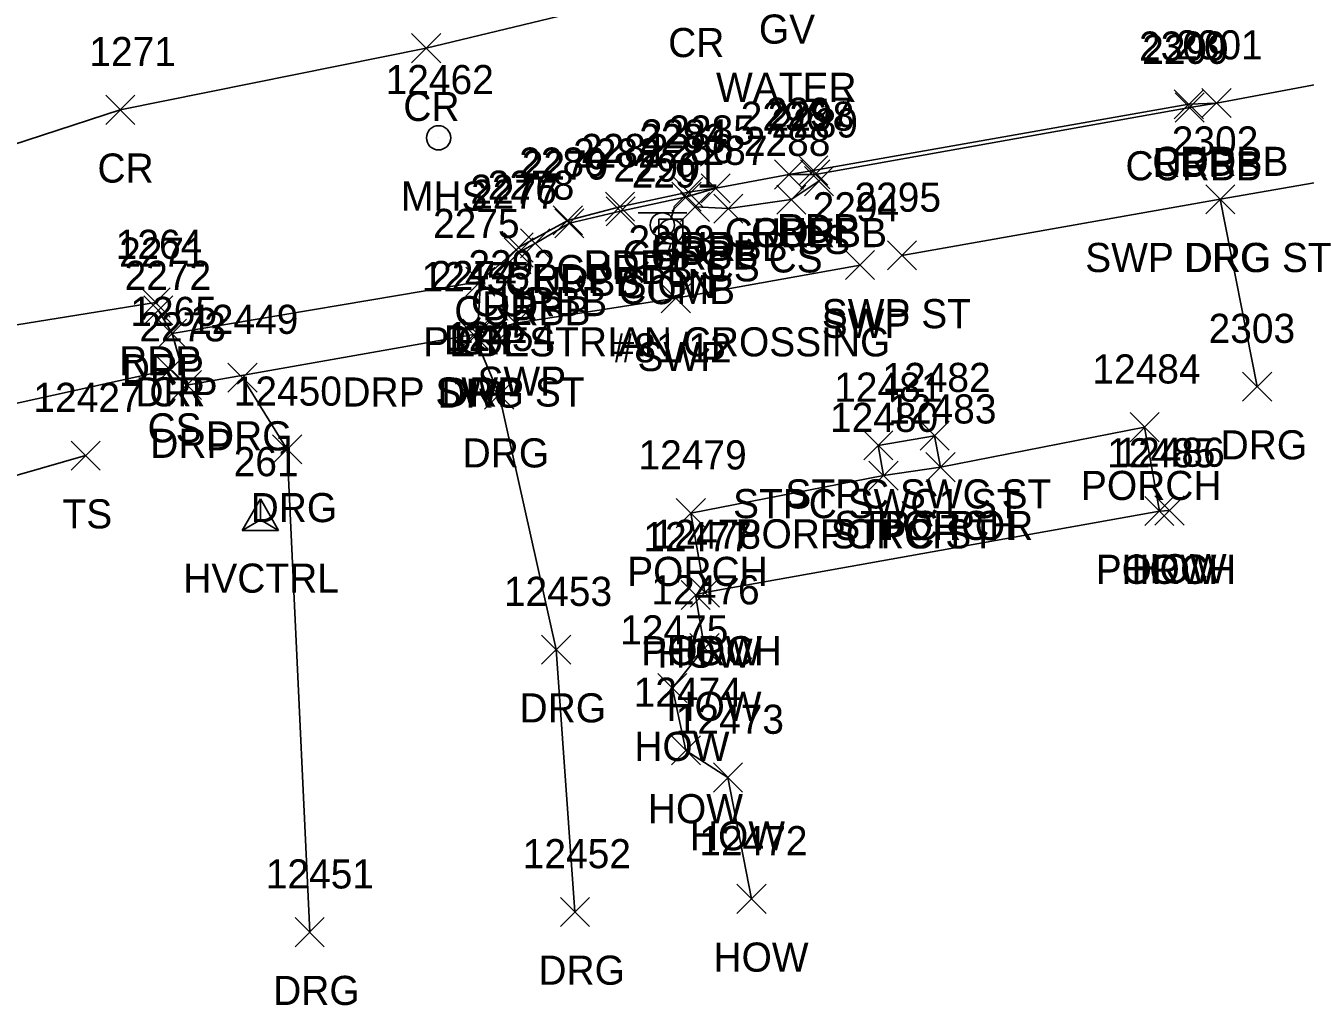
# Model space of a CAD drawing. Extents: x 1769141 to 1770817, y 735471 to 742405.
# Drawn here: x 1770233.5 to 1770321.5, y 741060.7 to 741128 of the extents above; entities that cross this region are included whole.
import ezdxf

# ---------------------------------------------------------------- set-up
doc = ezdxf.new("R2010")
doc.units = 0
for name, color, linetype in [('C_A', 7, 'Continuous'), ('C_I', 7, 'Continuous'), ('CPSM', 7, 'Continuous'), ('L_A', 7, 'Continuous'), ('L_I', 7, 'Continuous'), ('L_TIC', 7, 'Continuous'), ('LBC', 7, 'Continuous'), ('LBF', 7, 'Continuous'), ('LELB', 7, 'Continuous'), ('P_A', 7, 'Continuous'), ('P_I', 7, 'Continuous'), ('P_TIC', 7, 'Continuous'), ('PET', 7, 'Continuous'), ('PRC', 7, 'Continuous'), ('R_A', 7, 'Continuous'), ('R_I', 7, 'Continuous'), ('R_TIC', 7, 'Continuous'), ('RC', 7, 'Continuous'), ('RDG', 7, 'Continuous'), ('RDP', 7, 'Continuous'), ('RSW', 7, 'Continuous'), ('S_A', 7, 'Continuous'), ('S_C', 7, 'Continuous'), ('S_I', 7, 'Continuous'), ('SSGN', 7, 'Continuous'), ('U_A', 7, 'Continuous'), ('U_C', 7, 'Continuous'), ('U_I', 7, 'Continuous'), ('UP', 7, 'Continuous'), ('USMH', 7, 'Continuous')]:
    doc.layers.add(name, color=color, linetype=linetype)

msp = doc.modelspace()

# ---------------------------------------------------------------- linework, layer by layer
at = {"layer": 'CPSM'}
for p, q in [((1770248.416, 741093.366), (1770249.666, 741095.531)), ((1770250.916, 741093.366), (1770249.666, 741095.531)), ((1770249.666, 741094.087), (1770249.666, 741095.531)), ((1770248.416, 741093.366), (1770249.666, 741094.087)), ((1770249.666, 741094.087), (1770249.666, 741094.087)), ((1770249.666, 741094.087), (1770250.916, 741093.366)), ((1770248.416, 741093.366), (1770250.916, 741093.366))]:
    msp.add_line(p, q, dxfattribs=at)
at = {"layer": 'L_TIC'}
for points in [[(1770287.046, 741116.348), (1770289.046, 741118.348)], [(1770289.046, 741116.348), (1770287.046, 741118.348)], [(1770285.142, 741115.079), (1770287.142, 741117.079)], [(1770287.142, 741115.079), (1770285.142, 741117.079)], [(1770278.529, 741114.58), (1770280.529, 741116.58)], [(1770280.529, 741114.58), (1770278.529, 741116.58)], [(1770280.82, 741114.467), (1770282.82, 741116.467)], [(1770282.82, 741114.467), (1770280.82, 741116.467)], [(1770242.463, 741103.407), (1770244.463, 741105.407)], [(1770244.463, 741103.407), (1770242.463, 741105.407)], [(1770309.427, 741099.454), (1770311.427, 741101.454)], [(1770311.427, 741099.454), (1770309.427, 741101.454)], [(1770291.118, 741098.206), (1770293.118, 741100.206)], [(1770293.118, 741098.206), (1770291.118, 741100.206)], [(1770294.996, 741098.871), (1770296.996, 741100.871)], [(1770296.996, 741098.871), (1770294.996, 741100.871)], [(1770236.65, 741097.502), (1770238.65, 741099.502)], [(1770238.65, 741097.502), (1770236.65, 741099.502)], [(1770295.4, 741096.707), (1770297.4, 741098.707)], [(1770297.4, 741096.707), (1770295.4, 741098.707)], [(1770295.4, 741096.707), (1770297.4, 741098.707)], [(1770297.4, 741096.707), (1770295.4, 741098.707)], [(1770291.48, 741096.13), (1770293.48, 741098.13)], [(1770293.48, 741096.13), (1770291.48, 741098.13)], [(1770291.48, 741096.13), (1770293.48, 741098.13)], [(1770293.48, 741096.13), (1770291.48, 741098.13)], [(1770311.137, 741093.735), (1770313.137, 741095.735)], [(1770313.137, 741093.735), (1770311.137, 741095.735)], [(1770278.244, 741093.551), (1770280.244, 741095.551)], [(1770280.244, 741093.551), (1770278.244, 741095.551)], [(1770310.442, 741093.695), (1770312.442, 741095.695)], [(1770312.442, 741093.695), (1770310.442, 741095.695)], [(1770310.442, 741093.695), (1770312.442, 741095.695)], [(1770312.442, 741093.695), (1770310.442, 741095.695)], [(1770278.568, 741087.934), (1770280.568, 741089.934)], [(1770280.568, 741087.934), (1770278.568, 741089.934)], [(1770279.211, 741088.103), (1770281.211, 741090.103)], [(1770281.211, 741088.103), (1770279.211, 741090.103)], [(1770279.211, 741088.103), (1770281.211, 741090.103)], [(1770281.211, 741088.103), (1770279.211, 741090.103)], [(1770279.177, 741084.285), (1770281.177, 741086.285)], [(1770281.177, 741084.285), (1770279.177, 741086.285)], [(1770276.972, 741081.536), (1770278.972, 741083.536)], [(1770278.972, 741081.536), (1770276.972, 741083.536)], [(1770277.902, 741077.257), (1770279.902, 741079.257)], [(1770279.902, 741077.257), (1770277.902, 741079.257)], [(1770280.793, 741075.397), (1770282.793, 741077.397)], [(1770282.793, 741075.397), (1770280.793, 741077.397)], [(1770282.41, 741067.062), (1770284.41, 741069.062)], [(1770284.41, 741067.062), (1770282.41, 741069.062)]]:
    msp.add_lwpolyline(points, dxfattribs=at)
at = {"layer": 'LBC'}
msp.add_lwpolyline([(1770283.41, 741068.062), (1770281.793, 741076.397), (1770278.902, 741078.257), (1770277.972, 741082.536), (1770280.177, 741085.285), (1770279.568, 741088.934), (1770280.211, 741089.103), (1770311.442, 741094.695), (1770312.137, 741094.735)], dxfattribs=at)
at = {"layer": 'LBF'}
for points in [[(1770280.211, 741089.103), (1770279.244, 741094.551), (1770292.48, 741097.13), (1770296.4, 741097.707), (1770310.427, 741100.454), (1770311.442, 741094.695)], [(1770292.48, 741097.13), (1770292.118, 741099.206), (1770295.996, 741099.871), (1770296.4, 741097.707)]]:
    msp.add_lwpolyline(points, dxfattribs=at)
at = {"layer": 'LELB'}
for points in [[(1770279.529, 741115.58), (1770281.82, 741115.467), (1770286.142, 741116.079), (1770288.046, 741117.348)], [(1770243.463, 741104.407), (1770229.687, 741101.394), (1770215.801, 741098.707), (1770201.283, 741096.576), (1770194.054, 741092.056)], [(1770198.356, 741087.687), (1770219.162, 741093.21), (1770237.65, 741098.502)]]:
    msp.add_lwpolyline(points, dxfattribs=at)
at = {"layer": 'P_TIC'}
for points in [[(1770260.05, 741125.482), (1770262.05, 741127.482)], [(1770262.05, 741125.482), (1770260.05, 741127.482)], [(1770239.032, 741121.25), (1770241.032, 741123.25)], [(1770241.032, 741121.25), (1770239.032, 741123.25)], [(1770312.467, 741121.626), (1770314.467, 741123.626)], [(1770314.467, 741121.626), (1770312.467, 741123.626)], [(1770314.364, 741121.711), (1770316.364, 741123.711)], [(1770316.364, 741121.711), (1770314.364, 741123.711)], [(1770284.981, 741116.808), (1770286.981, 741118.808)], [(1770286.981, 741116.808), (1770284.981, 741118.808)], [(1770286.654, 741117.086), (1770288.654, 741119.086)], [(1770288.654, 741117.086), (1770286.654, 741119.086)], [(1770279.95, 741115.863), (1770281.95, 741117.863)], [(1770281.95, 741115.863), (1770279.95, 741117.863)], [(1770278.067, 741115.593), (1770280.067, 741117.593)], [(1770280.067, 741115.593), (1770278.067, 741117.593)], [(1770273.372, 741114.598), (1770275.372, 741116.598)], [(1770275.372, 741114.598), (1770273.372, 741116.598)], [(1770269.791, 741113.659), (1770271.791, 741115.659)], [(1770271.791, 741113.659), (1770269.791, 741115.659)], [(1770266.402, 741111.794), (1770268.402, 741113.794)], [(1770268.402, 741111.794), (1770266.402, 741113.794)], [(1770263.782, 741109.448), (1770265.782, 741111.448)], [(1770265.782, 741109.448), (1770263.782, 741111.448)], [(1770241.459, 741108.014), (1770243.459, 741110.014)], [(1770243.459, 741108.014), (1770241.459, 741110.014)], [(1770242.587, 741105.881), (1770244.587, 741107.881)], [(1770244.587, 741105.881), (1770242.587, 741107.881)]]:
    msp.add_lwpolyline(points, dxfattribs=at)
at = {"layer": 'PET'}
for points in [[(1770267.402, 741112.794), (1770270.791, 741114.659), (1770274.372, 741115.598), (1770279.067, 741116.593), (1770280.95, 741116.863), (1770285.981, 741117.808), (1770287.654, 741118.086), (1770313.467, 741122.626), (1770315.364, 741122.711), (1770327.096, 741124.908), (1770329.296, 741125.38), (1770348.677, 741128.817), (1770381.373, 741134.55), (1770423.899, 741142.105)], [(1770147.313, 741084.024), (1770155.707, 741087.796), (1770162.831, 741089.417), (1770171.891, 741090.698), (1770171.852, 741092.948), (1770186.159, 741098.793), (1770191.681, 741100.4), (1770200.669, 741101.89), (1770211.537, 741103.665), (1770225.504, 741106.293), (1770242.459, 741109.014)]]:
    msp.add_lwpolyline(points, dxfattribs=at)
at = {"layer": 'PRC'}
for points in [[(1770422.288, 741154.401), (1770391.031, 741148.9), (1770351.212, 741141.744), (1770324.852, 741137.505), (1770305.015, 741134.401), (1770279.252, 741130.869), (1770261.05, 741126.482)], [(1770261.05, 741126.482), (1770240.032, 741122.25)], [(1770240.032, 741122.25), (1770223.985, 741117.036), (1770202.573, 741111.843), (1770190.375, 741109.654), (1770171.332, 741105.227), (1770161.251, 741102.786), (1770155.587, 741101.56), (1770143.323, 741098.229)], [(1770243.587, 741106.881), (1770264.782, 741110.448)]]:
    msp.add_lwpolyline(points, dxfattribs=at)
at = {"layer": 'R_TIC'}
for points in [[(1770312.527, 741121.406), (1770314.527, 741123.406)], [(1770314.527, 741121.406), (1770312.527, 741123.406)], [(1770314.364, 741121.711), (1770316.364, 741123.711)], [(1770316.364, 741121.711), (1770314.364, 741123.711)], [(1770284.981, 741116.808), (1770286.981, 741118.808)], [(1770286.981, 741116.808), (1770284.981, 741118.808)], [(1770286.782, 741116.816), (1770288.782, 741118.816)], [(1770288.782, 741116.816), (1770286.782, 741118.816)], [(1770279.95, 741115.863), (1770281.95, 741117.863)], [(1770281.95, 741115.863), (1770279.95, 741117.863)], [(1770277.946, 741115.281), (1770279.946, 741117.281)], [(1770279.946, 741115.281), (1770277.946, 741117.281)], [(1770314.627, 741115.109), (1770316.627, 741117.109)], [(1770316.627, 741115.109), (1770314.627, 741117.109)], [(1770314.627, 741115.109), (1770316.627, 741117.109)], [(1770316.627, 741115.109), (1770314.627, 741117.109)], [(1770273.411, 741114.283), (1770275.411, 741116.283)], [(1770275.411, 741114.283), (1770273.411, 741116.283)], [(1770269.894, 741113.459), (1770271.894, 741115.459)], [(1770271.894, 741113.459), (1770269.894, 741115.459)], [(1770266.402, 741111.794), (1770268.402, 741113.794)], [(1770268.402, 741111.794), (1770266.402, 741113.794)], [(1770266.404, 741111.454), (1770268.404, 741113.454)], [(1770268.404, 741111.454), (1770266.404, 741113.454)], [(1770267.543, 741112.075), (1770269.543, 741114.075)], [(1770269.543, 741112.075), (1770267.543, 741114.075)], [(1770289.871, 741110.589), (1770291.871, 741112.589)], [(1770291.871, 741110.589), (1770289.871, 741112.589)], [(1770292.745, 741111.25), (1770294.745, 741113.25)], [(1770294.745, 741111.25), (1770292.745, 741113.25)], [(1770263.782, 741109.448), (1770265.782, 741111.448)], [(1770265.782, 741109.448), (1770263.782, 741111.448)], [(1770277.211, 741108.307), (1770279.211, 741110.307)], [(1770279.211, 741108.307), (1770277.211, 741110.307)], [(1770241.648, 741107.478), (1770243.648, 741109.478)], [(1770243.648, 741107.478), (1770241.648, 741109.478)], [(1770266.216, 741106.609), (1770268.216, 741108.609)], [(1770268.216, 741106.609), (1770266.216, 741108.609)], [(1770242.587, 741105.881), (1770244.587, 741107.881)], [(1770244.587, 741105.881), (1770242.587, 741107.881)], [(1770263.332, 741105.793), (1770265.332, 741107.793)], [(1770265.332, 741105.793), (1770263.332, 741107.793)], [(1770263.583, 741105.871), (1770265.583, 741107.871)], [(1770265.583, 741105.871), (1770263.583, 741107.871)], [(1770263.583, 741105.871), (1770265.583, 741107.871)], [(1770265.583, 741105.871), (1770263.583, 741107.871)], [(1770247.432, 741102.862), (1770249.432, 741104.862)], [(1770249.432, 741102.862), (1770247.432, 741104.862)], [(1770243.607, 741102.346), (1770245.607, 741104.346)], [(1770245.607, 741102.346), (1770243.607, 741104.346)], [(1770265.071, 741101.689), (1770267.071, 741103.689)], [(1770267.071, 741101.689), (1770265.071, 741103.689)], [(1770317.158, 741102.242), (1770319.158, 741104.242)], [(1770319.158, 741102.242), (1770317.158, 741104.242)], [(1770291.118, 741098.206), (1770293.118, 741100.206)], [(1770293.118, 741098.206), (1770291.118, 741100.206)], [(1770294.996, 741098.871), (1770296.996, 741100.871)], [(1770296.996, 741098.871), (1770294.996, 741100.871)], [(1770250.502, 741097.933), (1770252.502, 741099.933)], [(1770252.502, 741097.933), (1770250.502, 741099.933)], [(1770268.984, 741084.179), (1770270.984, 741086.179)], [(1770270.984, 741084.179), (1770268.984, 741086.179)], [(1770270.278, 741066.165), (1770272.278, 741068.165)], [(1770272.278, 741066.165), (1770270.278, 741068.165)], [(1770252.053, 741064.775), (1770254.053, 741066.775)], [(1770254.053, 741064.775), (1770252.053, 741066.775)]]:
    msp.add_lwpolyline(points, dxfattribs=at)
at = {"layer": 'RC'}
for points in [[(1770285.981, 741117.808), (1770287.782, 741117.816), (1770313.527, 741122.406), (1770315.364, 741122.711)], [(1770267.404, 741112.454), (1770268.543, 741113.075), (1770270.894, 741114.459), (1770274.411, 741115.283), (1770278.946, 741116.281), (1770280.95, 741116.863)]]:
    msp.add_lwpolyline(points, dxfattribs=at)
at = {"layer": 'RDG'}
for points in [[(1770315.627, 741116.109), (1770318.158, 741103.242)], [(1770271.278, 741067.165), (1770269.984, 741085.179), (1770266.071, 741102.689), (1770264.332, 741106.793)], [(1770248.432, 741103.862), (1770251.502, 741098.933), (1770253.053, 741065.775)]]:
    msp.add_lwpolyline(points, dxfattribs=at)
at = {"layer": 'RDP'}
msp.add_lwpolyline([(1770242.648, 741108.478), (1770243.587, 741106.881), (1770244.607, 741103.346), (1770264.583, 741106.871), (1770264.782, 741110.448), (1770267.402, 741112.794)], dxfattribs=at)
at = {"layer": 'RSW'}
for points in [[(1770293.745, 741112.25), (1770315.627, 741116.109), (1770329.06, 741118.452), (1770346.845, 741121.665), (1770347.607, 741118.02), (1770351.128, 741119.098), (1770350.707, 741122.277), (1770366.412, 741124.952), (1770367.41, 741121.56), (1770370.433, 741121.809), (1770369.828, 741125.643), (1770385.176, 741128.353), (1770423.885, 741135.428)], [(1770264.583, 741106.871), (1770267.216, 741107.609), (1770278.211, 741109.307), (1770290.871, 741111.589)]]:
    msp.add_lwpolyline(points, dxfattribs=at)
at = {"layer": 'SSGN'}
for p, q in [((1770275.628, 741115.17), (1770278.962, 741115.17)), ((1770277.275, 741114.337), (1770277.275, 741114.337))]:
    msp.add_line(p, q, dxfattribs=at)
msp.add_circle((1770277.275, 741114.337), 0.833, dxfattribs=at)
at = {"layer": 'UP'}
for p, q in [((1770278.118, 741115.571), (1770277.868, 741114.737)), ((1770277.034, 741113.071), (1770277.034, 741114.737)), ((1770277.034, 741114.737), (1770278.701, 741114.737)), ((1770278.701, 741114.737), (1770278.701, 741113.071)), ((1770277.868, 741113.904), (1770277.868, 741113.904)), ((1770278.701, 741113.071), (1770277.034, 741113.071)), ((1770277.618, 741112.237), (1770277.868, 741113.071))]:
    msp.add_line(p, q, dxfattribs=at)
msp.add_circle((1770277.868, 741113.904), 0.833, dxfattribs=at)
at = {"layer": 'USMH'}
for p, q in [((1770261.904, 741120.327), (1770261.904, 741120.327)), ((1770262.737, 741120.327), (1770262.737, 741120.327))]:
    msp.add_line(p, q, dxfattribs=at)
msp.add_circle((1770261.904, 741120.327), 0.833, dxfattribs=at)

# ---------------------------------------------------------------- texts
at = {"layer": 'C_A'}
msp.add_text('HVCTRL', height=2, dxfattribs=at).set_placement((1770244.359, 741089.087))
at = {"layer": 'C_I'}
msp.add_text('261', height=2, dxfattribs=at).set_placement((1770247.823, 741097.087))
at = {"layer": 'L_A'}
for s, p in [('CS', (1770286.487, 741112.348)), ('CS', (1770277.97, 741110.58)), ('CS', (1770280.261, 741110.467)), ('CS', (1770284.583, 741111.079)), ('CS', (1770241.904, 741099.407)), ('PORCH', (1770306.049, 741095.454)), ('STPC SWC ST', (1770285.736, 741094.871)), ('STPC SWC1 ST', (1770282.142, 741094.206)), ('TS', (1770236.06, 741093.502)), ('POR STPC ST', (1770282.315, 741092.13)), ('PORCH', (1770288.102, 741092.13)), ('STPC POR', (1770289.101, 741092.707)), ('PORCH', (1770292.022, 741092.707)), ('PORCH', (1770274.866, 741089.551)), ('PORCH', (1770307.064, 741089.695)), ('HOW', (1770308.828, 741089.695)), ('HOW', (1770309.523, 741089.735)), ('PORCH', (1770275.833, 741084.103)), ('HOW', (1770277.597, 741084.103)), ('HOW', (1770276.954, 741083.934)), ('HOW', (1770277.563, 741080.285)), ('HOW', (1770275.358, 741077.536)), ('HOW', (1770276.288, 741073.257)), ('HOW', (1770279.179, 741071.397)), ('HOW', (1770280.796, 741063.062))]:
    msp.add_text(s, height=2, dxfattribs=at).set_placement(p)
at = {"layer": 'L_I'}
for s, p in [('2289', (1770284.779, 741120.348)), ('2286', (1770276.214, 741118.58)), ('2287', (1770278.56, 741118.467)), ('2288', (1770282.882, 741119.079)), ('1265', (1770240.723, 741107.407)), ('12484', (1770306.836, 741103.454)), ('12482', (1770292.406, 741102.871)), ('12481', (1770289.095, 741102.206)), ('12427', (1770234.06, 741101.502)), ('12480', (1770288.803, 741100.13)), ('12480', (1770288.803, 741100.13)), ('12483', (1770292.81, 741100.707)), ('12483', (1770292.81, 741100.707)), ('12479', (1770275.646, 741097.551)), ('12485', (1770307.851, 741097.695)), ('12485', (1770307.851, 741097.695)), ('12486', (1770308.492, 741097.735)), ('12477', (1770275.978, 741091.934)), ('12478', (1770276.621, 741092.103)), ('12478', (1770276.621, 741092.103)), ('12476', (1770276.532, 741088.285)), ('12475', (1770274.382, 741085.536)), ('12474', (1770275.312, 741081.257)), ('12473', (1770278.203, 741079.397)), ('12472', (1770279.82, 741071.062))]:
    msp.add_text(s, height=2, dxfattribs=at).set_placement(p)
at = {"layer": 'P_A'}
for s, p in [('CR', (1770277.685, 741125.869)), ('CR', (1770259.483, 741121.482)), ('RDP', (1770310.955, 741117.626)), ('RDP', (1770312.852, 741117.711)), ('CR', (1770238.465, 741117.25)), ('RDP', (1770285.143, 741113.086)), ('RDP', (1770283.47, 741112.808)), ('RDP', (1770276.555, 741111.593)), ('RDP', (1770278.438, 741111.863)), ('RDP', (1770271.861, 741110.598)), ('RDP', (1770268.279, 741109.659)), ('RDP', (1770264.89, 741107.794)), ('CR', (1770263.215, 741105.448)), ('RDP', (1770239.947, 741104.014)), ('CR', (1770242.02, 741101.881))]:
    msp.add_text(s, height=2, dxfattribs=at).set_placement(p)
at = {"layer": 'P_I'}
for s, p in [('2300', (1770310.042, 741125.626)), ('2301', (1770312.592, 741125.711)), ('1271', (1770237.906, 741125.25)), ('2297', (1770284.395, 741121.086)), ('2296', (1770282.667, 741120.808)), ('2284', (1770275.807, 741119.593)), ('2285', (1770277.69, 741119.863)), ('2281', (1770271.68, 741118.598)), ('2280', (1770267.444, 741117.659)), ('2276', (1770264.087, 741115.794)), ('2275', (1770261.522, 741113.448)), ('1264', (1770239.719, 741112.014)), ('2272', (1770240.327, 741109.881))]:
    msp.add_text(s, height=2, dxfattribs=at).set_placement(p)
at = {"layer": 'R_A'}
for s, p in [('CURBB', (1770310.946, 741117.711)), ('CURBB', (1770309.11, 741117.406)), ('CURBB', (1770281.564, 741112.808)), ('CURBB', (1770283.364, 741112.816)), ('CURBB', (1770274.529, 741111.281)), ('CURBB', (1770276.532, 741111.863)), ('SWP DRG ST', (1770306.344, 741111.109)), ('DRG', (1770313.116, 741111.109)), ('CURBB', (1770269.993, 741110.283)), ('CURBB', (1770266.477, 741109.459)), ('CURBB', (1770264.126, 741108.075)), ('DRP', (1770264.89, 741107.794)), ('CURBB', (1770262.987, 741107.454)), ('SWP ST', (1770288.241, 741107.25)), ('SWP', (1770288.233, 741106.589)), ('DRP', (1770262.27, 741105.448)), ('SWP', (1770275.573, 741104.307)), ('DRP', (1770240.137, 741103.478)), ('SWP', (1770264.578, 741102.609)), ('DRP', (1770241.075, 741101.881)), ('DRP SWP ST', (1770255.299, 741101.871)), ('DRG', (1770261.82, 741101.793)), ('DRP', (1770262.071, 741101.871)), ('DRP', (1770242.095, 741098.346)), ('DRG', (1770245.921, 741098.862)), ('DRG', (1770315.647, 741098.242)), ('DRG', (1770263.559, 741097.689)), ('STPC SWC ST', (1770285.736, 741094.871)), ('DRG', (1770248.991, 741093.933)), ('STPC SWC1 ST', (1770282.142, 741094.206)), ('DRG', (1770267.473, 741080.179)), ('DRG', (1770268.766, 741062.165)), ('DRG', (1770250.541, 741060.775))]:
    msp.add_text(s, height=2, dxfattribs=at).set_placement(p)
at = {"layer": 'R_I'}
for s, p in [('2299', (1770310.259, 741125.406)), ('2301', (1770312.592, 741125.711)), ('2296', (1770282.667, 741120.808)), ('2298', (1770284.522, 741120.816)), ('2283', (1770275.686, 741119.281)), ('2285', (1770277.69, 741119.863)), ('2302', (1770312.289, 741119.109)), ('2302', (1770312.289, 741119.109)), ('2279', (1770267.627, 741117.459)), ('2282', (1770271.151, 741118.283)), ('2276', (1770264.087, 741115.794)), ('2278', (1770265.284, 741116.075)), ('2277', (1770264.144, 741115.454)), ('2295', (1770290.485, 741115.25)), ('2294', (1770287.611, 741114.589)), ('2275', (1770261.522, 741113.448)), ('2293', (1770274.951, 741112.307)), ('2271', (1770239.956, 741111.478)), ('2292', (1770263.956, 741110.609)), ('2272', (1770240.327, 741109.881)), ('12455', (1770260.742, 741109.793)), ('2274', (1770261.323, 741109.871)), ('2274', (1770261.323, 741109.871)), ('2273', (1770241.348, 741106.346)), ('12449', (1770244.834, 741106.862)), ('2303', (1770314.82, 741106.242)), ('12454', (1770262.481, 741105.689)), ('12482', (1770292.406, 741102.871)), ('12450', (1770247.826, 741101.933)), ('12481', (1770289.095, 741102.206)), ('12453', (1770266.394, 741088.179)), ('12452', (1770267.688, 741070.165)), ('12451', (1770250.03, 741068.775))]:
    msp.add_text(s, height=2, dxfattribs=at).set_placement(p)
at = {"layer": 'S_A'}
msp.add_text('SIGN', height=2, dxfattribs=at).set_placement((1770274.413, 741109.316))
at = {"layer": 'S_C'}
msp.add_text('PEDESTRIAN CROSSING', height=2, dxfattribs=at).set_placement((1770260.854, 741105.316))
at = {"layer": 'S_I'}
msp.add_text('2290', height=2, dxfattribs=at).set_placement((1770273.909, 741117.316))
at = {"layer": 'U_A'}
for s, p in [('GV', (1770283.917, 741126.794)), ('MHS', (1770259.321, 741115.327)), ('COMB', (1770274.253, 741108.904))]:
    msp.add_text(s, height=2, dxfattribs=at).set_placement(p)
at = {"layer": 'U_C'}
for s, p in [('WATER', (1770280.972, 741122.794)), ('#81/12', (1770273.868, 741104.904))]:
    msp.add_text(s, height=2, dxfattribs=at).set_placement(p)
at = {"layer": 'U_I'}
for s, p in [('12462', (1770258.266, 741123.327)), ('2291', (1770275.175, 741116.904))]:
    msp.add_text(s, height=2, dxfattribs=at).set_placement(p)

doc.saveas('drawing.dxf')
